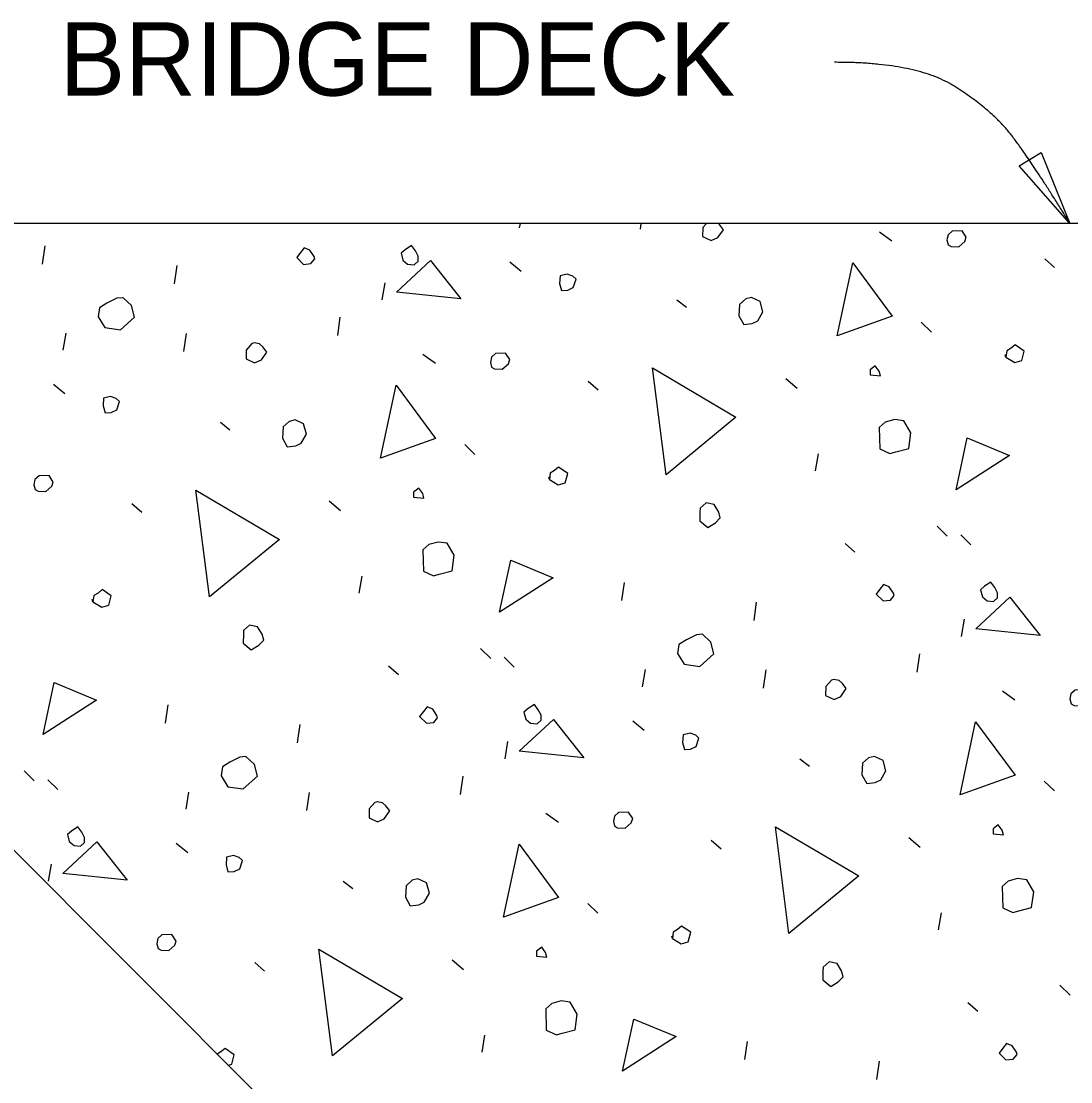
# Model space of a CAD drawing. Extents: x -1660015.2 to -1659984.9, y 2580594.2 to 2580616.7.
# Drawn here: x -1659993.208 to -1659991.042, y 2580612.425 to 2580614.613 of the extents above; entities that cross this region are included whole.
import ezdxf

# ---------------------------------------------------------------- set-up
doc = ezdxf.new("R2010")
doc.units = 0
for name, color, linetype in [('Miscellaneous', 7, 'Continuous'), ('Miscellaneous3', 7, 'Continuous'), ('PlotBorder_dp', 7, 'Continuous'), ('SheetLines_dp', 7, 'Continuous')]:
    doc.layers.add(name, color=color, linetype=linetype)

msp = doc.modelspace()

# ---------------------------------------------------------------- linework, layer by layer
at = {"layer": 'Miscellaneous'}
for p, q in [((-1659992.1793, 2580614.1865), (-1659992.1778, 2580614.1954)), ((-1659991.93, 2580614.1834), (-1659991.9283, 2580614.1954)), ((-1659991.4369, 2580614.1784), (-1659991.4111, 2580614.1594)), ((-1659993.1635, 2580614.1117), (-1659993.1581, 2580614.1494)), ((-1659992.8911, 2580614.0708), (-1659992.8857, 2580614.1085)), ((-1659992.1994, 2580614.1164), (-1659992.176, 2580614.0968)), ((-1659991.0958, 2580614.1222), (-1659991.0755, 2580614.1044)), ((-1659992.4631, 2580614.038), (-1659992.457, 2580614.0733)), ((-1659991.8548, 2580614.0379), (-1659991.8352, 2580614.0225)), ((-1659992.5546, 2580613.9643), (-1659992.5492, 2580614.002)), ((-1659991.3507, 2580613.9918), (-1659991.3297, 2580613.9715)), ((-1659993.1211, 2580613.9341), (-1659993.115, 2580613.9694)), ((-1659992.8718, 2580613.9311), (-1659992.8664, 2580613.9687)), ((-1659992.3787, 2580613.926), (-1659992.3529, 2580613.907)), ((-1659992.0376, 2580613.8699), (-1659992.0172, 2580613.852)), ((-1659991.6301, 2580613.8755), (-1659991.6068, 2580613.8559)), ((-1659993.1412, 2580613.8641), (-1659993.1178, 2580613.8444)), ((-1659992.7966, 2580613.7856), (-1659992.7769, 2580613.7701)), ((-1659992.2925, 2580613.7395), (-1659992.2715, 2580613.7192)), ((-1659991.5687, 2580613.6849), (-1659991.5626, 2580613.7202)), ((-1659992.9793, 2580613.6175), (-1659992.959, 2580613.5997)), ((-1659992.5719, 2580613.6232), (-1659992.5485, 2580613.6036)), ((-1659991.3182, 2580613.5709), (-1659991.2972, 2580613.5506)), ((-1659991.2693, 2580613.5529), (-1659991.2484, 2580613.5327)), ((-1659991.508, 2580613.5356), (-1659991.4877, 2580613.5177)), ((-1659992.5105, 2580613.4326), (-1659992.5044, 2580613.4679)), ((-1659991.9681, 2580613.4175), (-1659991.9627, 2580613.4551)), ((-1659991.6957, 2580613.3766), (-1659991.6903, 2580613.4142)), ((-1659991.2676, 2580613.3437), (-1659991.2616, 2580613.379)), ((-1659992.2599, 2580613.3185), (-1659992.239, 2580613.2983)), ((-1659992.2111, 2580613.3006), (-1659992.1902, 2580613.2803)), ((-1659991.3592, 2580613.27), (-1659991.3538, 2580613.3077)), ((-1659992.4498, 2580613.2832), (-1659992.4294, 2580613.2654)), ((-1659991.9257, 2580613.2399), (-1659991.9196, 2580613.2752)), ((-1659991.6764, 2580613.2368), (-1659991.671, 2580613.2745)), ((-1659991.1833, 2580613.2317), (-1659991.1575, 2580613.2128)), ((-1659992.9099, 2580613.1651), (-1659992.9044, 2580613.2028)), ((-1659991.9457, 2580613.1698), (-1659991.9224, 2580613.1502)), ((-1659992.6375, 2580613.1242), (-1659992.6321, 2580613.1619)), ((-1659992.2094, 2580613.0914), (-1659992.2033, 2580613.1267)), ((-1659991.6012, 2580613.0913), (-1659991.5815, 2580613.0759)), ((-1659993.2017, 2580613.0662), (-1659993.1808, 2580613.0459)), ((-1659992.301, 2580613.0177), (-1659992.2955, 2580613.0554)), ((-1659993.1529, 2580613.0482), (-1659993.1319, 2580613.028)), ((-1659991.0971, 2580613.0452), (-1659991.0761, 2580613.0249)), ((-1659992.8675, 2580612.9875), (-1659992.8614, 2580613.0228)), ((-1659992.6182, 2580612.9844), (-1659992.6127, 2580613.0221)), ((-1659992.1251, 2580612.9794), (-1659992.0993, 2580612.9604)), ((-1659991.3765, 2580612.9289), (-1659991.3531, 2580612.9093)), ((-1659992.8875, 2580612.9175), (-1659992.8641, 2580612.8978)), ((-1659991.7839, 2580612.9233), (-1659991.7636, 2580612.9054)), ((-1659993.1512, 2580612.839), (-1659993.1451, 2580612.8743)), ((-1659992.543, 2580612.839), (-1659992.5233, 2580612.8235)), ((-1659992.0388, 2580612.7929), (-1659992.0179, 2580612.7726)), ((-1659991.3151, 2580612.7383), (-1659991.309, 2580612.7736)), ((-1659992.7257, 2580612.6709), (-1659992.7054, 2580612.6531)), ((-1659992.3183, 2580612.6766), (-1659992.2949, 2580612.657)), ((-1659991.0645, 2580612.6243), (-1659991.0436, 2580612.604)), ((-1659991.2543, 2580612.589), (-1659991.234, 2580612.5711)), ((-1659992.2568, 2580612.486), (-1659992.2508, 2580612.5213)), ((-1659991.7144, 2580612.4708), (-1659991.709, 2580612.5085)), ((-1659991.4421, 2580612.4299), (-1659991.4366, 2580612.4676))]:
    msp.add_line(p, q, dxfattribs=at)
for points in [[(-1659991.8015, 2580614.1868), (-1659991.8018, 2580614.1686), (-1659991.7841, 2580614.1604), (-1659991.7703, 2580614.1667), (-1659991.759, 2580614.1826), (-1659991.7671, 2580614.1934), (-1659991.7693, 2580614.1954)], [(-1659991.794, 2580614.1954), (-1659991.8015, 2580614.1868)], [(-1659991.2952, 2580614.1516), (-1659991.2891, 2580614.1481), (-1659991.2733, 2580614.1471), (-1659991.2607, 2580614.1583), (-1659991.2578, 2580614.1668), (-1659991.2665, 2580614.18), (-1659991.2872, 2580614.1797), (-1659991.2955, 2580614.1722), (-1659991.2978, 2580614.1613), (-1659991.2952, 2580614.1516)], [(-1659992.4202, 2580614.1194), (-1659992.4103, 2580614.1116), (-1659992.397, 2580614.1101), (-1659992.3886, 2580614.1175), (-1659992.3888, 2580614.1278), (-1659992.3944, 2580614.1392), (-1659992.4025, 2580614.15), (-1659992.4157, 2580614.1413), (-1659992.424, 2580614.1339), (-1659992.4202, 2580614.1194)], [(-1659992.6392, 2580614.1254), (-1659992.625, 2580614.1111), (-1659992.6099, 2580614.1125), (-1659992.6021, 2580614.1224), (-1659992.6034, 2580614.1272), (-1659992.6121, 2580614.1404), (-1659992.6237, 2580614.145), (-1659992.6315, 2580614.1352), (-1659992.6392, 2580614.1254)], [(-1659992.4336, 2580614.0536), (-1659992.3632, 2580614.1191), (-1659992.3006, 2580614.0401), (-1659992.4336, 2580614.0536)], [(-1659991.5243, 2580613.9634), (-1659991.4922, 2580614.1144), (-1659991.411, 2580614.0041), (-1659991.5243, 2580613.9634)], [(-1659992.0967, 2580614.0714), (-1659992.0929, 2580614.057), (-1659992.0801, 2580614.0578), (-1659992.0687, 2580614.0634), (-1659992.0629, 2580614.0805), (-1659992.0697, 2580614.0864), (-1659992.0813, 2580614.0911), (-1659992.0958, 2580614.0872), (-1659992.0967, 2580614.0714)], [(-1659993.0489, 2580614.0027), (-1659993.0352, 2580613.9805), (-1659993.003, 2580613.9761), (-1659992.9737, 2580614.0021), (-1659992.9801, 2580614.0263), (-1659992.9974, 2580614.0423), (-1659993.0101, 2580614.0415), (-1659993.0306, 2580614.0309), (-1659993.0462, 2580614.0215), (-1659993.0489, 2580614.0027)], [(-1659991.7255, 2580614.0286), (-1659991.7269, 2580614.0049), (-1659991.7169, 2580613.9869), (-1659991.6994, 2580613.989), (-1659991.6879, 2580613.9946), (-1659991.6773, 2580614.013), (-1659991.6831, 2580614.0347), (-1659991.7009, 2580614.0429), (-1659991.7129, 2580614.0397), (-1659991.7255, 2580614.0286)], [(-1659992.7433, 2580613.9344), (-1659992.7436, 2580613.9162), (-1659992.7259, 2580613.908), (-1659992.712, 2580613.9143), (-1659992.7008, 2580613.9303), (-1659992.7089, 2580613.9411), (-1659992.7156, 2580613.947), (-1659992.7266, 2580613.9493), (-1659992.7314, 2580613.948), (-1659992.7433, 2580613.9344)], [(-1659991.1761, 2580613.9196), (-1659991.1577, 2580613.9089), (-1659991.1432, 2580613.9128), (-1659991.1381, 2580613.9323), (-1659991.1571, 2580613.9453), (-1659991.1654, 2580613.9379), (-1659991.1745, 2580613.9329), (-1659991.1761, 2580613.9196), (-1659991.1773, 2580613.9244)], [(-1659992.237, 2580613.8993), (-1659992.2308, 2580613.8957), (-1659992.2151, 2580613.8948), (-1659992.2025, 2580613.9059), (-1659992.1996, 2580613.9145), (-1659992.2083, 2580613.9277), (-1659992.2289, 2580613.9273), (-1659992.2373, 2580613.9199), (-1659992.2395, 2580613.9089), (-1659992.237, 2580613.8993)], [(-1659991.8773, 2580613.6773), (-1659991.9052, 2580613.8976), (-1659991.7331, 2580613.7962), (-1659991.8773, 2580613.6773)], [(-1659991.4562, 2580613.8833), (-1659991.435, 2580613.8812), (-1659991.4375, 2580613.8909), (-1659991.4456, 2580613.9017), (-1659991.4564, 2580613.8936), (-1659991.4562, 2580613.8833)], [(-1659992.4661, 2580613.7111), (-1659992.434, 2580613.862), (-1659992.3527, 2580613.7518), (-1659992.4661, 2580613.7111)], [(-1659993.0385, 2580613.8191), (-1659993.0346, 2580613.8046), (-1659993.0219, 2580613.8054), (-1659993.0105, 2580613.8111), (-1659993.0047, 2580613.8282), (-1659993.0115, 2580613.8341), (-1659993.0231, 2580613.8388), (-1659993.0376, 2580613.8349), (-1659993.0385, 2580613.8191)], [(-1659992.6673, 2580613.7762), (-1659992.6687, 2580613.7525), (-1659992.6587, 2580613.7345), (-1659992.6411, 2580613.7366), (-1659992.6297, 2580613.7423), (-1659992.6191, 2580613.7607), (-1659992.6249, 2580613.7824), (-1659992.6426, 2580613.7906), (-1659992.6547, 2580613.7873), (-1659992.6673, 2580613.7762)], [(-1659991.4374, 2580613.7745), (-1659991.4361, 2580613.7308), (-1659991.4153, 2580613.7209), (-1659991.4032, 2580613.7241), (-1659991.3766, 2580613.7312), (-1659991.3723, 2580613.7634), (-1659991.3867, 2580613.7881), (-1659991.4055, 2580613.7908), (-1659991.4249, 2580613.7856), (-1659991.4374, 2580613.7745)], [(-1659991.2788, 2580613.6461), (-1659991.2557, 2580613.7533), (-1659991.1684, 2580613.7171), (-1659991.2788, 2580613.6461)], [(-1659992.1178, 2580613.6672), (-1659992.0995, 2580613.6566), (-1659992.085, 2580613.6605), (-1659992.0798, 2580613.68), (-1659992.0989, 2580613.693), (-1659992.1072, 2580613.6856), (-1659992.1162, 2580613.6806), (-1659992.1178, 2580613.6672), (-1659992.1191, 2580613.672)], [(-1659993.1787, 2580613.6469), (-1659993.1726, 2580613.6434), (-1659993.1568, 2580613.6425), (-1659993.1443, 2580613.6536), (-1659993.1414, 2580613.6621), (-1659993.1501, 2580613.6753), (-1659993.1707, 2580613.675), (-1659993.1791, 2580613.6675), (-1659993.1813, 2580613.6566), (-1659993.1787, 2580613.6469)], [(-1659992.398, 2580613.631), (-1659992.3767, 2580613.6289), (-1659992.3793, 2580613.6386), (-1659992.3874, 2580613.6493), (-1659992.3982, 2580613.6413), (-1659992.398, 2580613.631)], [(-1659992.819, 2580613.425), (-1659992.847, 2580613.6452), (-1659992.6749, 2580613.5438), (-1659992.819, 2580613.425)], [(-1659991.8074, 2580613.6003), (-1659991.8077, 2580613.5821), (-1659991.7911, 2580613.5684), (-1659991.7755, 2580613.5778), (-1659991.7654, 2580613.5882), (-1659991.7686, 2580613.6003), (-1659991.778, 2580613.6159), (-1659991.7944, 2580613.6193), (-1659991.807, 2580613.6082), (-1659991.8074, 2580613.6003)], [(-1659992.3792, 2580613.5221), (-1659992.3778, 2580613.4785), (-1659992.3571, 2580613.4685), (-1659992.345, 2580613.4718), (-1659992.3184, 2580613.4789), (-1659992.3141, 2580613.5111), (-1659992.3285, 2580613.5357), (-1659992.3473, 2580613.5384), (-1659992.3666, 2580613.5332), (-1659992.3792, 2580613.5221)], [(-1659992.2206, 2580613.3938), (-1659992.1975, 2580613.5009), (-1659992.1102, 2580613.4648), (-1659992.2206, 2580613.3938)], [(-1659991.4438, 2580613.4311), (-1659991.4296, 2580613.4168), (-1659991.4144, 2580613.4183), (-1659991.4067, 2580613.4281), (-1659991.408, 2580613.4329), (-1659991.4167, 2580613.4461), (-1659991.4283, 2580613.4508), (-1659991.436, 2580613.441), (-1659991.4438, 2580613.4311)], [(-1659991.2247, 2580613.4251), (-1659991.2149, 2580613.4174), (-1659991.2015, 2580613.4158), (-1659991.1932, 2580613.4232), (-1659991.1933, 2580613.4335), (-1659991.199, 2580613.4449), (-1659991.2071, 2580613.4557), (-1659991.2203, 2580613.447), (-1659991.2286, 2580613.4396), (-1659991.2247, 2580613.4251)], [(-1659993.0596, 2580613.4149), (-1659993.0412, 2580613.4043), (-1659993.0267, 2580613.4081), (-1659993.0216, 2580613.4276), (-1659993.0406, 2580613.4406), (-1659993.049, 2580613.4332), (-1659993.058, 2580613.4282), (-1659993.0596, 2580613.4149), (-1659993.0609, 2580613.4197)], [(-1659991.2382, 2580613.3594), (-1659991.1677, 2580613.4249), (-1659991.1052, 2580613.3459), (-1659991.2382, 2580613.3594)], [(-1659992.7492, 2580613.3479), (-1659992.7495, 2580613.3297), (-1659992.7329, 2580613.316), (-1659992.7173, 2580613.3254), (-1659992.7072, 2580613.3359), (-1659992.7104, 2580613.348), (-1659992.7198, 2580613.3636), (-1659992.7362, 2580613.3669), (-1659992.7487, 2580613.3558), (-1659992.7492, 2580613.3479)], [(-1659991.8535, 2580613.3084), (-1659991.8397, 2580613.2862), (-1659991.8075, 2580613.2819), (-1659991.7783, 2580613.3079), (-1659991.7847, 2580613.332), (-1659991.802, 2580613.3481), (-1659991.8147, 2580613.3473), (-1659991.8351, 2580613.3366), (-1659991.8507, 2580613.3272), (-1659991.8535, 2580613.3084)], [(-1659991.5479, 2580613.2402), (-1659991.5482, 2580613.222), (-1659991.5305, 2580613.2138), (-1659991.5166, 2580613.2201), (-1659991.5054, 2580613.236), (-1659991.5134, 2580613.2468), (-1659991.5202, 2580613.2528), (-1659991.5312, 2580613.255), (-1659991.536, 2580613.2537), (-1659991.5479, 2580613.2402)], [(-1659993.1623, 2580613.1415), (-1659993.1393, 2580613.2486), (-1659993.052, 2580613.2124), (-1659993.1623, 2580613.1415)], [(-1659991.0415, 2580613.205), (-1659991.0354, 2580613.2015), (-1659991.0196, 2580613.2005), (-1659991.0071, 2580613.2117), (-1659991.0042, 2580613.2202), (-1659991.0129, 2580613.2334), (-1659991.0335, 2580613.2331), (-1659991.0419, 2580613.2256), (-1659991.0441, 2580613.2147), (-1659991.0415, 2580613.205)], [(-1659992.3855, 2580613.1788), (-1659992.3714, 2580613.1645), (-1659992.3562, 2580613.1659), (-1659992.3485, 2580613.1758), (-1659992.3498, 2580613.1806), (-1659992.3585, 2580613.1938), (-1659992.3701, 2580613.1984), (-1659992.3778, 2580613.1886), (-1659992.3855, 2580613.1788)], [(-1659992.1665, 2580613.1728), (-1659992.1567, 2580613.165), (-1659992.1433, 2580613.1634), (-1659992.135, 2580613.1709), (-1659992.1351, 2580613.1812), (-1659992.1408, 2580613.1926), (-1659992.1488, 2580613.2034), (-1659992.162, 2580613.1947), (-1659992.1704, 2580613.1872), (-1659992.1665, 2580613.1728)], [(-1659992.18, 2580613.107), (-1659992.1095, 2580613.1725), (-1659992.0469, 2580613.0935), (-1659992.18, 2580613.107)], [(-1659991.2706, 2580613.0168), (-1659991.2386, 2580613.1677), (-1659991.1573, 2580613.0575), (-1659991.2706, 2580613.0168)], [(-1659991.8431, 2580613.1248), (-1659991.8392, 2580613.1103), (-1659991.8265, 2580613.1112), (-1659991.8151, 2580613.1168), (-1659991.8093, 2580613.1339), (-1659991.8161, 2580613.1398), (-1659991.8277, 2580613.1445), (-1659991.8421, 2580613.1406), (-1659991.8431, 2580613.1248)], [(-1659992.7952, 2580613.0561), (-1659992.7815, 2580613.0338), (-1659992.7493, 2580613.0295), (-1659992.72, 2580613.0555), (-1659992.7265, 2580613.0797), (-1659992.7438, 2580613.0957), (-1659992.7565, 2580613.0949), (-1659992.7769, 2580613.0843), (-1659992.7925, 2580613.0749), (-1659992.7952, 2580613.0561)], [(-1659991.4718, 2580613.082), (-1659991.4733, 2580613.0583), (-1659991.4633, 2580613.0403), (-1659991.4457, 2580613.0424), (-1659991.4343, 2580613.048), (-1659991.4237, 2580613.0664), (-1659991.4295, 2580613.0881), (-1659991.4472, 2580613.0963), (-1659991.4593, 2580613.0931), (-1659991.4718, 2580613.082)], [(-1659992.4897, 2580612.9878), (-1659992.49, 2580612.9696), (-1659992.4722, 2580612.9614), (-1659992.4584, 2580612.9677), (-1659992.4471, 2580612.9837), (-1659992.4552, 2580612.9945), (-1659992.462, 2580613.0004), (-1659992.4729, 2580613.0027), (-1659992.4778, 2580613.0014), (-1659992.4897, 2580612.9878)], [(-1659991.9833, 2580612.9527), (-1659991.9772, 2580612.9491), (-1659991.9614, 2580612.9482), (-1659991.9489, 2580612.9593), (-1659991.946, 2580612.9679), (-1659991.9547, 2580612.9811), (-1659991.9753, 2580612.9807), (-1659991.9837, 2580612.9733), (-1659991.9859, 2580612.9623), (-1659991.9833, 2580612.9527)], [(-1659993.1083, 2580612.9204), (-1659993.0985, 2580612.9127), (-1659993.0851, 2580612.9111), (-1659993.0767, 2580612.9185), (-1659993.0769, 2580612.9288), (-1659993.0826, 2580612.9402), (-1659993.0906, 2580612.951), (-1659993.1038, 2580612.9423), (-1659993.1122, 2580612.9349), (-1659993.1083, 2580612.9204)], [(-1659991.6236, 2580612.7307), (-1659991.6516, 2580612.951), (-1659991.4795, 2580612.8496), (-1659991.6236, 2580612.7307)], [(-1659991.2026, 2580612.9367), (-1659991.1813, 2580612.9346), (-1659991.1839, 2580612.9443), (-1659991.192, 2580612.9551), (-1659991.2027, 2580612.947), (-1659991.2026, 2580612.9367)], [(-1659993.1217, 2580612.8547), (-1659993.0513, 2580612.9202), (-1659992.9887, 2580612.8412), (-1659993.1217, 2580612.8547)], [(-1659992.2124, 2580612.7645), (-1659992.1804, 2580612.9154), (-1659992.0991, 2580612.8052), (-1659992.2124, 2580612.7645)], [(-1659992.7849, 2580612.8725), (-1659992.781, 2580612.858), (-1659992.7683, 2580612.8588), (-1659992.7568, 2580612.8645), (-1659992.7511, 2580612.8815), (-1659992.7578, 2580612.8875), (-1659992.7694, 2580612.8921), (-1659992.7839, 2580612.8883), (-1659992.7849, 2580612.8725)], [(-1659992.4136, 2580612.8296), (-1659992.415, 2580612.8059), (-1659992.405, 2580612.7879), (-1659992.3875, 2580612.79), (-1659992.3761, 2580612.7957), (-1659992.3655, 2580612.814), (-1659992.3713, 2580612.8358), (-1659992.389, 2580612.844), (-1659992.4011, 2580612.8407), (-1659992.4136, 2580612.8296)], [(-1659991.1838, 2580612.8279), (-1659991.1824, 2580612.7842), (-1659991.1616, 2580612.7743), (-1659991.1496, 2580612.7775), (-1659991.123, 2580612.7846), (-1659991.1187, 2580612.8168), (-1659991.1331, 2580612.8414), (-1659991.1519, 2580612.8442), (-1659991.1712, 2580612.839), (-1659991.1838, 2580612.8279)], [(-1659992.9251, 2580612.7003), (-1659992.919, 2580612.6968), (-1659992.9032, 2580612.6958), (-1659992.8906, 2580612.707), (-1659992.8877, 2580612.7155), (-1659992.8965, 2580612.7287), (-1659992.9171, 2580612.7284), (-1659992.9254, 2580612.7209), (-1659992.9277, 2580612.71), (-1659992.9251, 2580612.7003)], [(-1659991.8642, 2580612.7206), (-1659991.8458, 2580612.71), (-1659991.8313, 2580612.7139), (-1659991.8262, 2580612.7334), (-1659991.8452, 2580612.7464), (-1659991.8536, 2580612.739), (-1659991.8626, 2580612.734), (-1659991.8642, 2580612.7206), (-1659991.8655, 2580612.7254)], [(-1659992.5654, 2580612.4784), (-1659992.5933, 2580612.6986), (-1659992.4212, 2580612.5972), (-1659992.5654, 2580612.4784)], [(-1659992.1444, 2580612.6844), (-1659992.1231, 2580612.6823), (-1659992.1257, 2580612.6919), (-1659992.1337, 2580612.7027), (-1659992.1445, 2580612.6947), (-1659992.1444, 2580612.6844)], [(-1659991.5538, 2580612.6537), (-1659991.5541, 2580612.6355), (-1659991.5375, 2580612.6218), (-1659991.5219, 2580612.6311), (-1659991.5117, 2580612.6416), (-1659991.515, 2580612.6537), (-1659991.5243, 2580612.6693), (-1659991.5408, 2580612.6727), (-1659991.5533, 2580612.6615), (-1659991.5538, 2580612.6537)], [(-1659992.1255, 2580612.5755), (-1659992.1242, 2580612.5319), (-1659992.1034, 2580612.5219), (-1659992.0913, 2580612.5251), (-1659992.0648, 2580612.5323), (-1659992.0605, 2580612.5645), (-1659992.0748, 2580612.5891), (-1659992.0937, 2580612.5918), (-1659992.113, 2580612.5866), (-1659992.1255, 2580612.5755)], [(-1659991.9669, 2580612.4472), (-1659991.9439, 2580612.5543), (-1659991.8565, 2580612.5182), (-1659991.9669, 2580612.4472)], [(-1659992.7802, 2580612.4596), (-1659992.7731, 2580612.4615), (-1659992.768, 2580612.481), (-1659992.787, 2580612.494), (-1659992.7954, 2580612.4866), (-1659992.803, 2580612.4824)], [(-1659991.1901, 2580612.4845), (-1659991.1759, 2580612.4702), (-1659991.1608, 2580612.4717), (-1659991.1531, 2580612.4815), (-1659991.1544, 2580612.4863), (-1659991.1631, 2580612.4995), (-1659991.1747, 2580612.5042), (-1659991.1824, 2580612.4943), (-1659991.1901, 2580612.4845)]]:
    msp.add_lwpolyline(points, dxfattribs=at)
at = {"layer": 'Miscellaneous3'}
for p, q in [((-1659989.5159, 2580614.1954), (-1659994.2928, 2580614.1954)), ((-1659992.6826, 2580612.3621), (-1659993.5576, 2580613.2371))]:
    msp.add_line(p, q, dxfattribs=at)
at = {"layer": 'SheetLines_dp'}
msp.add_lwpolyline([(-1659991.0439, 2580614.1953), (-1659991.1485, 2580614.3142), (-1659991.1035, 2580614.342)], close=True, dxfattribs=at)
msp.add_open_spline([(-1659991.0439, 2580614.1954), (-1659991.126, 2580614.3281), (-1659991.2066, 2580614.431), (-1659991.3618, 2580614.5278), (-1659991.5294, 2580614.5278)], degree=2, dxfattribs=at)

# ---------------------------------------------------------------- texts
at = {"layer": 'PlotBorder_dp'}
msp.add_text('BRIDGE DECK', height=0.1512, dxfattribs=at).set_placement((-1659993.128, 2580614.4591))

doc.saveas('drawing.dxf')
